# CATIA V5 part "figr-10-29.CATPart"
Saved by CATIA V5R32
Part number: Part1
Bounding box of the stored display mesh (mm): x -60 to 70, y 0 to 100.393, z 0 to 0
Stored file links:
  D:\PROJECTS\Project 2022\CATIA V5 6R 2022\Resources\Part Files\c10_catia_v5_6r2022_prt\c10_catia_v5_6r2022_prt\figr-10-29.CATPart
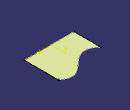
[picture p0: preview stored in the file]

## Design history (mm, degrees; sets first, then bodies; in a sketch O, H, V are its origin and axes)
Set1
  Sweep1: type Segment, GuideCrv (Sketch1; Sketch2), Length1 0, Length2 0
Body1 (main body)
  Sketch1 on xy-plane, origin (0, 0, 0), H (1, 0, 0), V (0, 1, 0)
    line L1 (-60, 0) -> (70, 0)
    point P1 (-60, 0)
    coincidence: P1 H
    horizontal: L1 H
  Sketch2 on xy-plane, origin (0, 0, 0), H (1, 0, 0), V (0, 1, 0)
    spline S1 through (-60, 70) (-20, 60) (40, 100) (70, 90)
